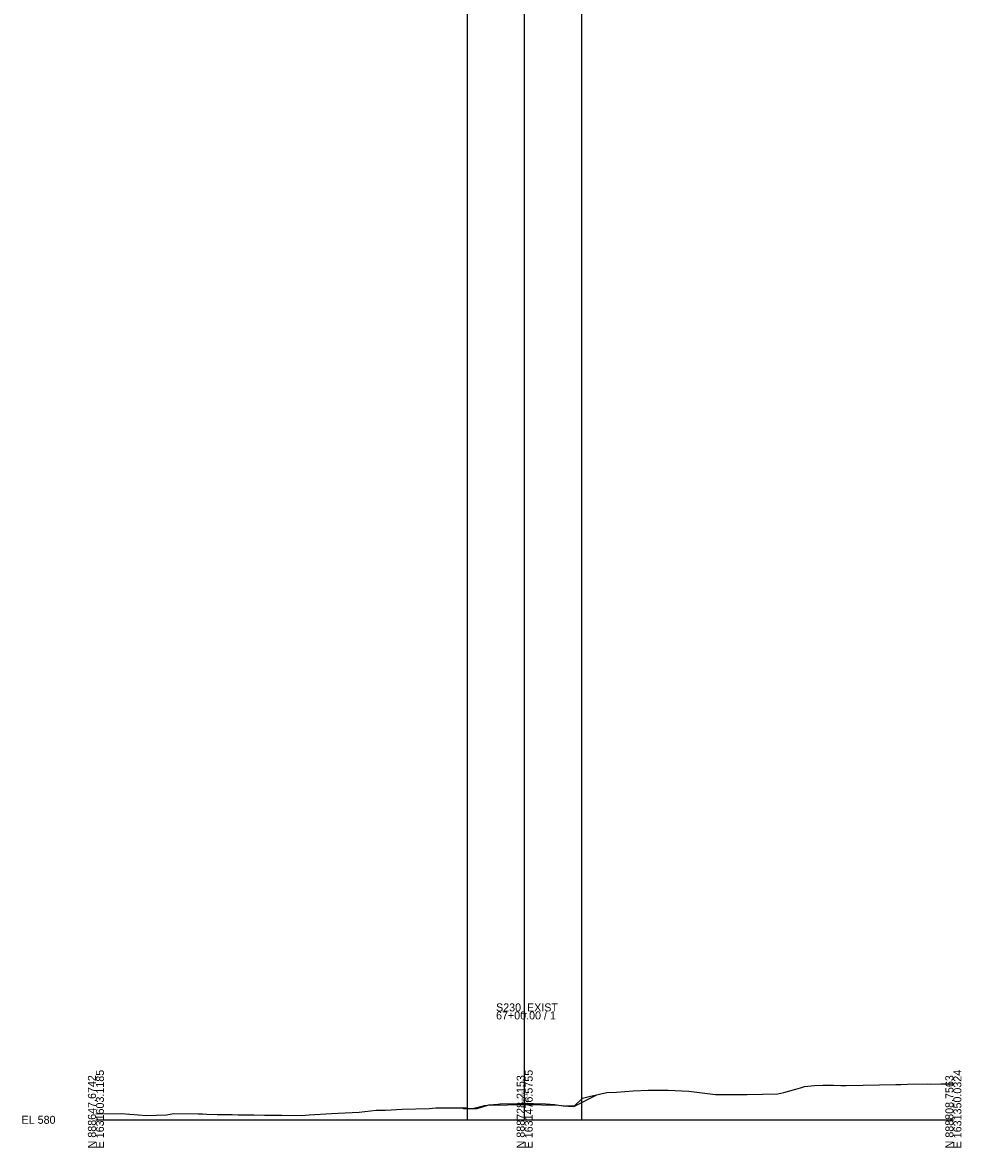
# Model space of a CAD drawing. Extents: x 1631115 to 1631443, y 885974 to 892071.
# Drawn here: x 1631114.8 to 1631443.3, y 885974 to 886367.5 of the extents above; entities that cross this region are included whole.
import ezdxf

# ---------------------------------------------------------------- set-up
doc = ezdxf.new("R2010")
doc.units = 0
for name, color, linetype in [('Default', 7, 'Continuous'), ('RD_GPK_XS_Cell', 7, 'Continuous'), ('RD_XS_EarthShd', 7, 'Continuous'), ('RD_XS_ExGround', 7, 'Continuous'), ('RD_XS_Pave', 7, 'Continuous'), ('RD_XS_TieSlope', 7, 'Continuous'), ('RD_XS_TX_Elev_EX', 7, 'Continuous'), ('RD_XS_TX_Elev_PR', 7, 'Continuous')]:
    doc.layers.add(name, color=color, linetype=linetype)

msp = doc.modelspace()

# ---------------------------------------------------------------- linework, layer by layer
at = {"layer": 'Default'}
for p, q in [((1631270.47, 885983.65), (1631270.47, 892068.63)), ((1631290.47, 885983.65), (1631290.47, 892068.63)), ((1631310.47, 885983.65), (1631310.47, 892068.63))]:
    msp.add_line(p, q, dxfattribs=at)
at = {"layer": 'RD_GPK_XS_Cell'}
for p, q in [((1631290.47, 885983.65), (1631290.47, 886021.57)), ((1631140.47, 885983.65), (1631290.47, 885983.65)), ((1631290.47, 885983.65), (1631440.47, 885983.65))]:
    msp.add_line(p, q, dxfattribs=at)
at = {"layer": 'RD_XS_EarthShd'}
for p, q in [((1631278.47, 885988.73), (1631276.47, 885988.57)), ((1631302.47, 885988.73), (1631304.47, 885988.57))]:
    msp.add_line(p, q, dxfattribs=at)
at = {"layer": 'RD_XS_ExGround'}
msp.add_lwpolyline([(1631140.47, 885985.7), (1631149.45, 885985.83), (1631158.2, 885985.13), (1631165.13, 885985.44), (1631167.75, 885985.8), (1631176.22, 885985.77), (1631177.72, 885985.72), (1631179.31, 885985.65), (1631182.84, 885985.55), (1631188.1, 885985.5), (1631190.21, 885985.4), (1631195.7, 885985.34), (1631199.4, 885985.26), (1631204.71, 885985.28), (1631205.55, 885985.27), (1631212.29, 885985.14), (1631215.11, 885985.44), (1631222.9, 885985.82), (1631225.24, 885985.93), (1631232.61, 885986.29), (1631238.57, 885986.97), (1631239.69, 885987.03), (1631241.77, 885987.05), (1631247.59, 885987.32), (1631257.03, 885987.64), (1631259.45, 885987.85), (1631266.59, 885987.79), (1631269.91, 885987.78), (1631271.21, 885987.43), (1631273.83, 885987.63), (1631277.96, 885988.89), (1631281.05, 885989.17), (1631281.9, 885989.27), (1631289.06, 885989.31), (1631290.47, 885989.32), (1631293.55, 885989.33), (1631297.91, 885989.29), (1631300.88, 885989.06), (1631303.91, 885988.51), (1631307.66, 885988.34), (1631310.71, 885991.27), (1631313.03, 885991.76), (1631319.23, 885993.18), (1631322.58, 885993.35), (1631328.43, 885993.73), (1631333.63, 885994.05), (1631334.93, 885994.07), (1631336.91, 885994.05), (1631340.74, 885994.01), (1631347.87, 885993.67), (1631357.3, 885992.55), (1631363.91, 885992.53), (1631368.35, 885992.49), (1631379.04, 885992.76), (1631381.18, 885993.17), (1631385.3, 885994.33), (1631386.98, 885994.88), (1631388.4, 885995.28), (1631391.92, 885995.67), (1631394.83, 885995.8), (1631398.5, 885995.74), (1631401.06, 885995.62), (1631402.94, 885995.7), (1631408.9, 885995.8), (1631420.3, 885995.98), (1631422.04, 885995.99), (1631424.39, 885996.16), (1631431.38, 885996.2), (1631432.6, 885996.16), (1631436.11, 885996.25), (1631439.28, 885996.29), (1631440.47, 885996.26)], dxfattribs=at)
at = {"layer": 'RD_XS_Pave'}
for p, q in [((1631278.47, 885988.73), (1631290.47, 885988.97)), ((1631290.47, 885988.97), (1631302.47, 885988.73))]:
    msp.add_line(p, q, dxfattribs=at)
at = {"layer": 'RD_XS_TieSlope'}
for p, q in [((1631307.91, 885988.46), (1631315.75, 885992.38)), ((1631269.21, 885987.51), (1631268.66, 885987.78)), ((1631272.21, 885987.51), (1631269.21, 885987.51)), ((1631276.47, 885988.57), (1631272.21, 885987.51)), ((1631304.47, 885988.57), (1631304.91, 885988.46)), ((1631307.91, 885988.46), (1631304.91, 885988.46))]:
    msp.add_line(p, q, dxfattribs=at)

# ---------------------------------------------------------------- texts
at = {"layer": 'RD_GPK_XS_Cell'}
for s, p in [('S230_EXIST', (1631280.47, 886021.57)), ('67+00.00 / 1', (1631280.47, 886018.77)), ('EL 580', (1631114.47, 885982.25))]:
    msp.add_text(s, height=2.8, dxfattribs=at).set_placement(p)
for s, p in [('N 888647.6742', (1631140.47, 885973.65)), ('E 1631603.1185', (1631143.27, 885973.65)), ('N 888728.2153', (1631290.47, 885973.65)), ('E 1631476.5755', (1631293.27, 885973.65)), ('N 888808.7563', (1631440.47, 885973.65)), ('E 1631350.0324', (1631443.27, 885973.65))]:
    msp.add_text(s, height=2.8, rotation=90, dxfattribs=at).set_placement(p)
at = {"layer": 'RD_XS_TX_Elev_EX'}
msp.add_text('585.66', height=1, rotation=90, dxfattribs=at).set_placement((1631290.37, 885989.42))
at = {"layer": 'RD_XS_TX_Elev_PR'}
msp.add_text(' 585.32', height=1, rotation=90, dxfattribs=at).set_placement((1631291.47, 885988.97))

doc.saveas('drawing.dxf')
